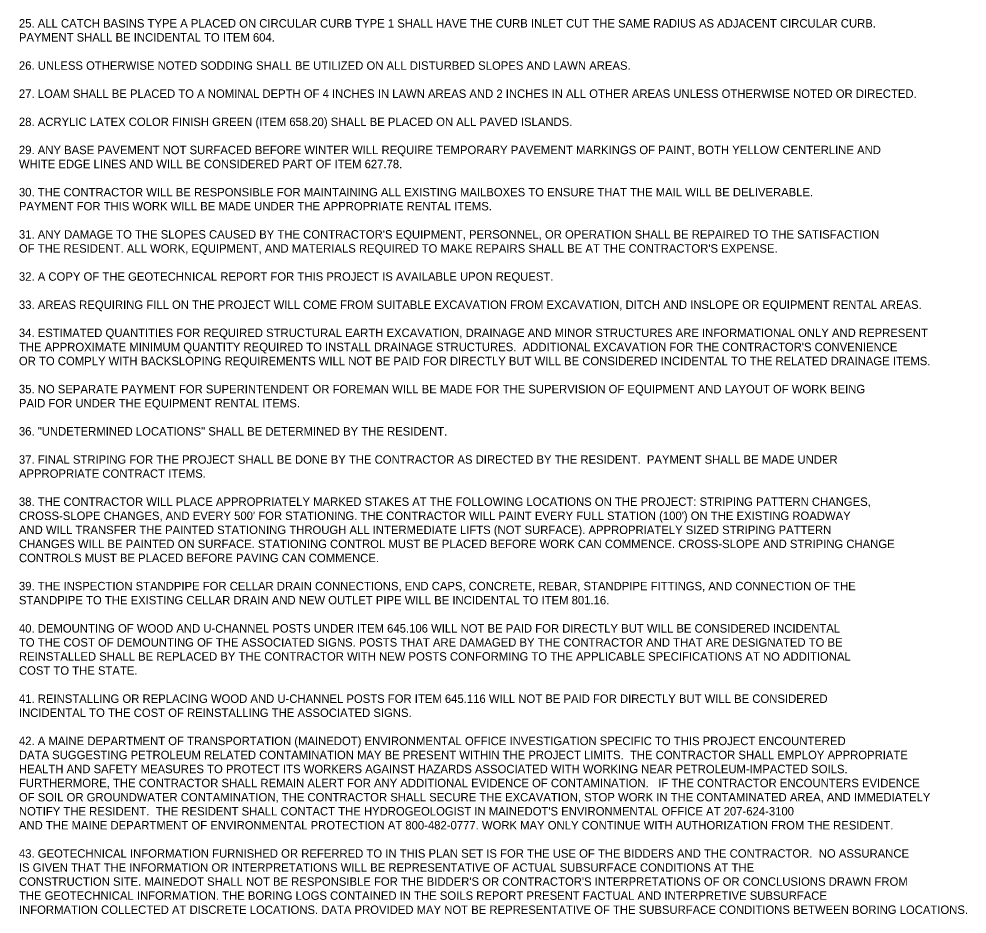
# Model space of a CAD drawing. Extents: x -0.13 to 5.88, y -0.37 to 1.78.
# Drawn here: x 4.829 to 5.882, y -0.373 to 0.621 of the extents above; entities that cross this region are included whole.
import ezdxf

# ---------------------------------------------------------------- set-up
doc = ezdxf.new("R2010")
doc.units = 0
doc.layers.add('ANNOTATION', color=7, linetype='Continuous')

msp = doc.modelspace()

# ---------------------------------------------------------------- texts
at = {"layer": 'ANNOTATION'}
for s, p in [('25. ALL CATCH BASINS TYPE A PLACED ON CIRCULAR CURB TYPE 1 SHALL HAVE THE CURB INLET CUT THE SAME RADIUS AS ADJACENT CIRCULAR CURB.', (4.8293, 0.6114)), ('PAYMENT SHALL BE INCIDENTAL TO ITEM 604.', (4.8293, 0.5958)), ('26. UNLESS OTHERWISE NOTED SODDING SHALL BE UTILIZED ON ALL DISTURBED SLOPES AND LAWN AREAS.', (4.8293, 0.5645)), ('27. LOAM SHALL BE PLACED TO A NOMINAL DEPTH OF 4 INCHES IN LAWN AREAS AND 2 INCHES IN ALL OTHER AREAS UNLESS OTHERWISE NOTED OR DIRECTED.', (4.8293, 0.5333)), ('28. ACRYLIC LATEX COLOR FINISH GREEN (ITEM 658.20) SHALL BE PLACED ON ALL PAVED ISLANDS.', (4.8293, 0.502)), ('29. ANY BASE PAVEMENT NOT SURFACED BEFORE WINTER WILL REQUIRE TEMPORARY PAVEMENT MARKINGS OF PAINT, BOTH YELLOW CENTERLINE AND', (4.8293, 0.4708)), ('WHITE EDGE LINES AND WILL BE CONSIDERED PART OF ITEM 627.78.', (4.8293, 0.4552)), ('30. THE CONTRACTOR WILL BE RESPONSIBLE FOR MAINTAINING ALL EXISTING MAILBOXES TO ENSURE THAT THE MAIL WILL BE DELIVERABLE.', (4.8293, 0.4239)), ('PAYMENT FOR THIS WORK WILL BE MADE UNDER THE APPROPRIATE RENTAL ITEMS.', (4.8293, 0.4083)), ("31. ANY DAMAGE TO THE SLOPES CAUSED BY THE CONTRACTOR'S EQUIPMENT, PERSONNEL, OR OPERATION SHALL BE REPAIRED TO THE SATISFACTION", (4.8293, 0.377)), ("OF THE RESIDENT. ALL WORK, EQUIPMENT, AND MATERIALS REQUIRED TO MAKE REPAIRS SHALL BE AT THE CONTRACTOR'S EXPENSE. ", (4.8293, 0.3614)), ('32. A COPY OF THE GEOTECHNICAL REPORT FOR THIS PROJECT IS AVAILABLE UPON REQUEST.  ', (4.8293, 0.3302)), ('33. AREAS REQUIRING FILL ON THE PROJECT WILL COME FROM SUITABLE EXCAVATION FROM EXCAVATION, DITCH AND INSLOPE OR EQUIPMENT RENTAL AREAS.', (4.8293, 0.2989)), ('34. ESTIMATED QUANTITIES FOR REQUIRED STRUCTURAL EARTH EXCAVATION, DRAINAGE AND MINOR STRUCTURES ARE INFORMATIONAL ONLY AND REPRESENT', (4.8293, 0.2677)), ("THE APPROXIMATE MINIMUM QUANTITY REQUIRED TO INSTALL DRAINAGE STRUCTURES.  ADDITIONAL EXCAVATION FOR THE CONTRACTOR'S CONVENIENCE", (4.8293, 0.252)), ('OR TO COMPLY WITH BACKSLOPING REQUIREMENTS WILL NOT BE PAID FOR DIRECTLY BUT WILL BE CONSIDERED INCIDENTAL TO THE RELATED DRAINAGE ITEMS.  ', (4.8293, 0.2364)), ('35. NO SEPARATE PAYMENT FOR SUPERINTENDENT OR FOREMAN WILL BE MADE FOR THE SUPERVISION OF EQUIPMENT AND LAYOUT OF WORK BEING', (4.8293, 0.2052)), ('PAID FOR UNDER THE EQUIPMENT RENTAL ITEMS.', (4.8293, 0.1895)), ('36. "UNDETERMINED LOCATIONS" SHALL BE DETERMINED BY THE RESIDENT.', (4.8293, 0.1583)), ('37. FINAL STRIPING FOR THE PROJECT SHALL BE DONE BY THE CONTRACTOR AS DIRECTED BY THE RESIDENT.  PAYMENT SHALL BE MADE UNDER', (4.8293, 0.127)), ('APPROPRIATE CONTRACT ITEMS.', (4.8293, 0.1114)), ('38. THE CONTRACTOR WILL PLACE APPROPRIATELY MARKED STAKES AT THE FOLLOWING LOCATIONS ON THE PROJECT: STRIPING PATTERN CHANGES,', (4.8293, 0.0802)), ("CROSS-SLOPE CHANGES, AND EVERY 500' FOR STATIONING. THE CONTRACTOR WILL PAINT EVERY FULL STATION (100') ON THE EXISTING ROADWAY ", (4.8293, 0.0645)), ('AND WILL TRANSFER THE PAINTED STATIONING THROUGH ALL INTERMEDIATE LIFTS (NOT SURFACE). APPROPRIATELY SIZED STRIPING PATTERN', (4.8293, 0.0489)), ('CHANGES WILL BE PAINTED ON SURFACE. STATIONING CONTROL MUST BE PLACED BEFORE WORK CAN COMMENCE. CROSS-SLOPE AND STRIPING CHANGE ', (4.8293, 0.0333)), ('CONTROLS MUST BE PLACED BEFORE PAVING CAN COMMENCE.', (4.8293, 0.0177)), ('39. THE INSPECTION STANDPIPE FOR CELLAR DRAIN CONNECTIONS, END CAPS, CONCRETE, REBAR, STANDPIPE FITTINGS, AND CONNECTION OF THE', (4.8293, -0.0136)), ('STANDPIPE TO THE EXISTING CELLAR DRAIN AND NEW OUTLET PIPE WILL BE INCIDENTAL TO ITEM 801.16.', (4.8293, -0.0292)), ('40. DEMOUNTING OF WOOD AND U-CHANNEL POSTS UNDER ITEM 645.106 WILL NOT BE PAID FOR DIRECTLY BUT WILL BE CONSIDERED INCIDENTAL', (4.8293, -0.0605)), ('TO THE COST OF DEMOUNTING OF THE ASSOCIATED SIGNS. POSTS THAT ARE DAMAGED BY THE CONTRACTOR AND THAT ARE DESIGNATED TO BE ', (4.8293, -0.0761)), ('REINSTALLED SHALL BE REPLACED BY THE CONTRACTOR WITH NEW POSTS CONFORMING TO THE APPLICABLE SPECIFICATIONS AT NO ADDITIONAL', (4.8293, -0.0917)), ('COST TO THE STATE.', (4.8293, -0.1073)), ('41. REINSTALLING OR REPLACING WOOD AND U-CHANNEL POSTS FOR ITEM 645.116 WILL NOT BE PAID FOR DIRECTLY BUT WILL BE CONSIDERED', (4.8293, -0.1386)), ('INCIDENTAL TO THE COST OF REINSTALLING THE ASSOCIATED SIGNS.', (4.8293, -0.1542)), ('42. A MAINE DEPARTMENT OF TRANSPORTATION (MAINEDOT) ENVIRONMENTAL OFFICE INVESTIGATION SPECIFIC TO THIS PROJECT ENCOUNTERED', (4.8293, -0.1855)), ('DATA SUGGESTING PETROLEUM RELATED CONTAMINATION MAY BE PRESENT WITHIN THE PROJECT LIMITS.  THE CONTRACTOR SHALL EMPLOY APPROPRIATE ', (4.8293, -0.2011)), ('HEALTH AND SAFETY MEASURES TO PROTECT ITS WORKERS AGAINST HAZARDS ASSOCIATED WITH WORKING NEAR PETROLEUM-IMPACTED SOILS.', (4.8293, -0.2167)), ('FURTHERMORE, THE CONTRACTOR SHALL REMAIN ALERT FOR ANY ADDITIONAL EVIDENCE OF CONTAMINATION.   IF THE CONTRACTOR ENCOUNTERS EVIDENCE ', (4.8293, -0.2323)), ('OF SOIL OR GROUNDWATER CONTAMINATION, THE CONTRACTOR SHALL SECURE THE EXCAVATION, STOP WORK IN THE CONTAMINATED AREA, AND IMMEDIATELY', (4.8293, -0.248)), ("NOTIFY THE RESIDENT.  THE RESIDENT SHALL CONTACT THE HYDROGEOLOGIST IN MAINEDOT'S ENVIRONMENTAL OFFICE AT 207-624-3100 ", (4.8293, -0.2636)), ('AND THE MAINE DEPARTMENT OF ENVIRONMENTAL PROTECTION AT 800-482-0777. WORK MAY ONLY CONTINUE WITH AUTHORIZATION FROM THE RESIDENT.', (4.8293, -0.2792)), ('43. GEOTECHNICAL INFORMATION FURNISHED OR REFERRED TO IN THIS PLAN SET IS FOR THE USE OF THE BIDDERS AND THE CONTRACTOR.  NO ASSURANCE', (4.8293, -0.3105)), ('IS GIVEN THAT THE INFORMATION OR INTERPRETATIONS WILL BE REPRESENTATIVE OF ACTUAL SUBSURFACE CONDITIONS AT THE ', (4.8293, -0.3261)), ("CONSTRUCTION SITE. MAINEDOT SHALL NOT BE RESPONSIBLE FOR THE BIDDER'S OR CONTRACTOR'S INTERPRETATIONS OF OR CONCLUSIONS DRAWN FROM", (4.8293, -0.3417)), ('THE GEOTECHNICAL INFORMATION. THE BORING LOGS CONTAINED IN THE SOILS REPORT PRESENT FACTUAL AND INTERPRETIVE SUBSURFACE ', (4.8293, -0.3573)), ('INFORMATION COLLECTED AT DISCRETE LOCATIONS. DATA PROVIDED MAY NOT BE REPRESENTATIVE OF THE SUBSURFACE CONDITIONS BETWEEN BORING LOCATIONS.', (4.8293, -0.373))]:
    msp.add_text(s, height=0.009375, dxfattribs=at).set_placement(p)

doc.saveas('drawing.dxf')
